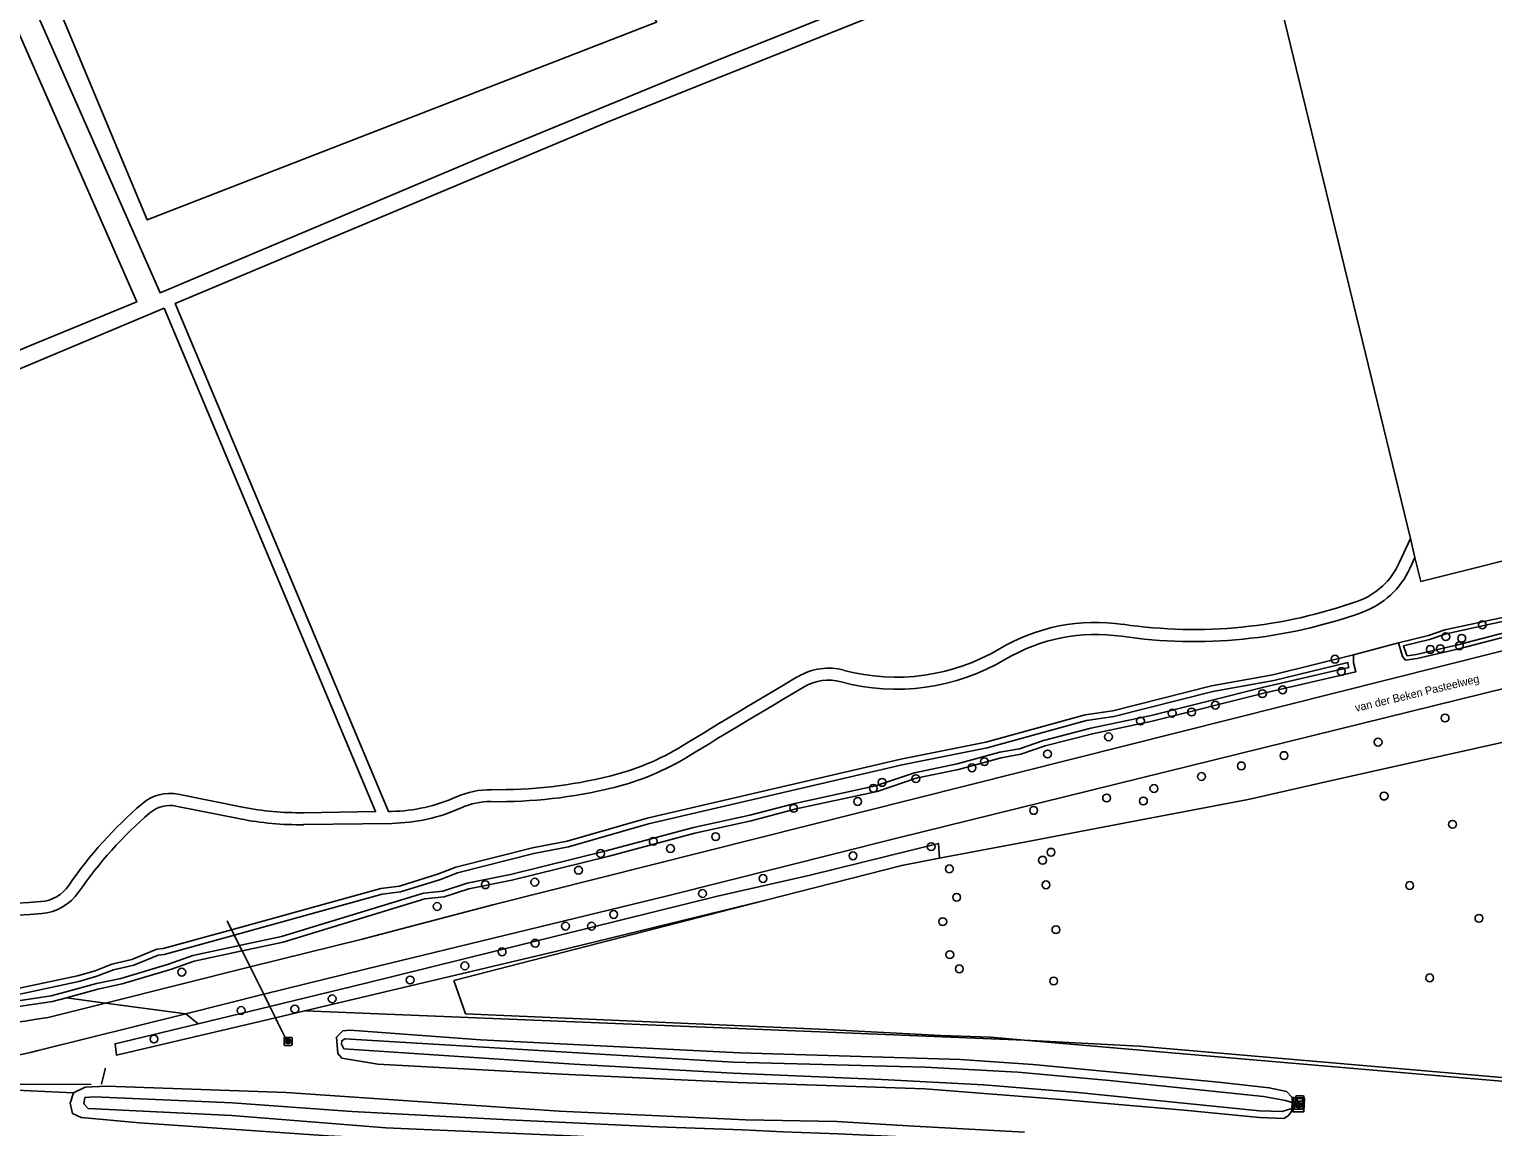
# Model space of a CAD drawing. Extents: x 161486 to 162249, y 379484 to 380829.
# Drawn here: x 161770.8 to 161953.6, y 379616.6 to 379753.8 of the extents above; entities that cross this region are included whole.
import ezdxf

# ---------------------------------------------------------------- set-up
doc = ezdxf.new("R2010")
doc.units = 0
for name, color, linetype in [('IMGEO_Berm_groen', 7, 'Continuous'), ('IMGEO_Boom', 7, 'Continuous'), ('IMGEO_Duiker', 7, 'Continuous'), ('IMGEO_Gemengd_bos', 7, 'Continuous'), ('IMGEO_Grasland_agrarisch', 7, 'Continuous'), ('IMGEO_Grasland_overig', 7, 'Continuous'), ('IMGEO_Groenvoorziening', 7, 'Continuous'), ('IMGEO_Hek', 7, 'Continuous'), ('IMGEO_Muur', 7, 'Continuous'), ('IMGEO_Openbare_ruimte_label', 7, 'Continuous'), ('IMGEO_Rijbaan_lokaal_gesloten', 7, 'Continuous'), ('IMGEO_Rioolput', 7, 'Continuous'), ('IMGEO_Verklikker', 7, 'Continuous'), ('IMGEO_Voetpad_onverhard', 7, 'Continuous'), ('IMGEO_Waterloop', 7, 'Continuous')]:
    doc.layers.add(name, color=color, linetype=linetype)

msp = doc.modelspace()

# ---------------------------------------------------------------- linework, layer by layer
at = {"layer": 'IMGEO_Berm_groen'}
for points in [[(161776.31, 379620.88), (161747.61, 379622.21)], [(161903.07, 379609.91), (161890.48, 379611.42), (161884.77, 379612.02), (161880.37, 379612.14), (161879.91, 379612.17), (161870.14, 379612.44), (161859.41, 379612.86), (161843.4, 379613.94), (161833.41, 379614.24), (161808.13, 379615.48), (161784.56, 379617.12), (161777.24, 379617.78), (161776.19, 379618.3), (161775.89, 379619.59), (161776.31, 379620.88)]]:
    msp.add_lwpolyline(points, dxfattribs=at)
at = {"layer": 'IMGEO_Boom'}
for centre in [(161952.32, 379679.35), (161947.75, 379677.87), (161949.74, 379677.66), (161945.82, 379676.28), (161947.07, 379676.37), (161949.45, 379676.73), (161933.91, 379675.05), (161934.69, 379673.52), (161924.84, 379670.75), (161927.36, 379671.22), (161913.57, 379668.31), (161915.99, 379668.45), (161918.96, 379669.31), (161909.61, 379667.33), (161947.66, 379667.7), (161905.61, 379665.36), (161939.29, 379664.69), (161897.99, 379663.21), (161927.53, 379663.01), (161888.55, 379661.49), (161890.09, 379662.25), (161922.21, 379661.72), (161877.32, 379659.66), (161881.54, 379660.13), (161917.22, 379660.39), (161874.27, 379657.27), (161876.22, 379658.92), (161905.37, 379657.71), (161909.97, 379657.34), (161911.28, 379658.9), (161940.04, 379657.95), (161866.27, 379656.42), (161896.26, 379656.16), (161948.59, 379654.42), (161848.73, 379652.3), (161856.53, 379652.88), (161842.15, 379650.77), (161850.88, 379651.39), (161873.68, 379650.49), (161883.45, 379651.63), (161897.37, 379649.93), (161898.42, 379650.93), (161839.39, 379648.68), (161885.73, 379648.86), (161827.75, 379646.87), (161833.93, 379647.19), (161862.44, 379647.65), (161897.8, 379646.86), (161943.23, 379646.77), (161854.89, 379645.77), (161886.64, 379645.29), (161821.73, 379644.16), (161843.78, 379643.16), (161951.89, 379642.68), (161837.77, 379641.7), (161841.02, 379641.7), (161884.9, 379642.25), (161899.04, 379641.25), (161833.98, 379639.56), (161829.84, 379638.49), (161885.78, 379638.13), (161789.82, 379635.95), (161825.19, 379636.73), (161886.97, 379636.36), (161818.35, 379634.97), (161898.75, 379634.85), (161945.74, 379635.23), (161808.62, 379632.62), (161797.24, 379631.15), (161803.95, 379631.34), (161786.35, 379627.59)]:
    msp.add_circle(centre, 0.489, dxfattribs=at)
at = {"layer": 'IMGEO_Duiker'}
msp.add_lwpolyline([(161803, 379627.29), (161801.8, 379629.69), (161801.52, 379630.26), (161800.82, 379631.67), (161800.07, 379633.18), (161798.36, 379636.6), (161797.37, 379638.6), (161796.05, 379641.24), (161795.5, 379642.36)], dxfattribs=at)
at = {"layer": 'IMGEO_Gemengd_bos'}
for points in [[(161943.9, 379687.78), (161944.62, 379684.78), (162013.75, 379702.1), (161991.56, 379794.76), (161957.01, 379782.13), (161923.86, 379770.32), (161943.32, 379690.14)], [(162103.51, 379717.85), (162082.78, 379712.68), (162051.49, 379704.49), (162044.8, 379703.03), (162038.52, 379701), (162023.08, 379696.83), (162017.46, 379695.48), (162006.48, 379693.16), (162002.89, 379692.16), (162000, 379691.35), (161987.15, 379688.34), (161980.69, 379686.35), (161978.48, 379685.95), (161967.35, 379683.24), (161958.16, 379681.3), (161955.64, 379680.45), (161947.64, 379678.71), (161945.57, 379678.02), (161941.82, 379677.08)], [(161941.82, 379677.08), (161936.2, 379675.58)], [(161936.2, 379675.58), (161926.12, 379673.12), (161918.49, 379671.72), (161906.13, 379668.59), (161902.69, 379668.11), (161890.29, 379664.69), (161879.67, 379662.57), (161847.96, 379655.2), (161837.99, 379652.3), (161833.64, 379651.47), (161824.05, 379649.06), (161821.89, 379648.22), (161817.01, 379646.69), (161814.71, 379646.39), (161796.05, 379641.24), (161787.51, 379638.89), (161786.71, 379638.8), (161783.6, 379637.54), (161781.07, 379636.94), (161778.99, 379636.12), (161776.8, 379635.49), (161768.36, 379633.68)]]:
    msp.add_lwpolyline(points, dxfattribs=at)
at = {"layer": 'IMGEO_Grasland_agrarisch'}
for points in [[(161811.73, 379837.85), (161816.17, 379831.42), (161818.13, 379826.38), (161849.14, 379754.65), (161785.51, 379729.95), (161751.67, 379810.84), (161811.73, 379837.85)], [(162006.1, 379676.56), (162000, 379675.13), (161969.1, 379667.86), (161938.33, 379660.99), (161932.77, 379659.73), (161923.05, 379657.53), (161905.99, 379654.28), (161895.12, 379652.21), (161884.24, 379650.14)], [(161805.2, 379631.13), (161895.06, 379627.46), (161979.42, 379620.21), (162016.57, 379617.14), (162018.11, 379616.78)]]:
    msp.add_lwpolyline(points, dxfattribs=at)
at = {"layer": 'IMGEO_Grasland_overig'}
for points in [[(161895.11, 379615.95), (161880.55, 379616.73), (161871.66, 379617.27), (161860.27, 379617.51), (161836.96, 379618.57), (161802.88, 379620.89), (161780.42, 379621.72), (161777.74, 379621.56), (161776.31, 379620.88)], [(161899.96, 379613.43), (161881.2, 379615.26), (161879.85, 379615.39), (161871.82, 379615.74), (161864.98, 379615.98), (161859.83, 379616.26), (161849.27, 379616.61), (161830.73, 379617.48), (161811.08, 379618.52), (161796.12, 379619.6), (161778.87, 379620.38), (161777.72, 379620.27), (161777.58, 379619.51), (161778.11, 379618.89), (161796.08, 379618.02), (161815.3, 379616.5), (161838.39, 379615.48), (161859.85, 379614.45), (161868.52, 379614.08), (161875.35, 379613.88), (161880.67, 379613.66), (161893.69, 379612.48), (161896.95, 379611.76), (161899.93, 379611.18)]]:
    msp.add_lwpolyline(points, dxfattribs=at)
at = {"layer": 'IMGEO_Groenvoorziening'}
for points in [[(161941.82, 379677.08), (161942.36, 379675.39), (161942.71, 379674.94), (161944.18, 379675.15), (161949.36, 379676.37), (161966.65, 379680.87), (161976.69, 379682.93), (162000, 379688.53), (162003.66, 379689.41), (162005.51, 379689.85), (162013.93, 379691.61), (162022.14, 379693.94), (162040.37, 379698.78), (162051.33, 379701.48), (162056.45, 379702.96), (162079.31, 379708.62), (162080.99, 379708.88), (162100.02, 379713.94), (162104.18, 379714.84)], [(161775.42, 379632.74), (161779.34, 379633.81), (161782.38, 379634.47), (161788.4, 379636.27), (161791.39, 379637.34), (161797.37, 379638.6), (161802.49, 379639.68), (161820.18, 379645.11), (161822.59, 379645.37), (161825.68, 379646.37), (161831.07, 379647.44), (161843.04, 379650.4), (161853.93, 379653.32), (161860.96, 379654.85), (161866.58, 379656.34), (161876.69, 379658.54), (161881.57, 379660.17), (161886.85, 379661.29), (161892.2, 379662.73), (161894.65, 379663.17), (161897.68, 379664.21), (161903.59, 379665.73), (161911.08, 379667.33), (161925.18, 379670.87), (161936.51, 379673.48), (161936.22, 379674.62), (161936.2, 379675.58)], [(161775.42, 379632.74), (161773.67, 379632.26), (161766.6, 379631.24), (161753.61, 379631.05), (161746.01, 379631.6), (161724.64, 379634.37), (161698.92, 379637.34), (161681.11, 379639.62), (161670.75, 379640.73), (161659.13, 379642.24), (161649.61, 379643.11), (161637.41, 379644.57), (161612.43, 379647.27), (161608.11, 379648.09), (161597.22, 379649.61), (161593, 379650.72), (161588.52, 379651.46), (161577.41, 379653.8), (161559.19, 379658.1), (161556.15, 379658.94)], [(161780.29, 379632.09), (161775.42, 379632.74)], [(161791.85, 379629.51), (161790.31, 379630.75)], [(161928.48, 379618.52), (161928.07, 379618.01), (161927.5, 379617.65), (161924.49, 379617.78), (161915.08, 379618.7), (161899.66, 379620.04), (161882.67, 379621.38), (161859.26, 379622.17), (161837.32, 379623.2), (161814.33, 379624.46), (161809.83, 379625.19), (161809.3, 379625.8), (161809.14, 379627.81), (161809.95, 379628.63), (161810.85, 379628.68), (161827.16, 379627.47), (161859.55, 379625.86), (161887.12, 379625.05), (161896.14, 379624.42), (161919.35, 379622.21), (161925.7, 379621.51), (161927.86, 379621.02), (161928.57, 379620.28)], [(161928.77, 379620.27), (161930.09, 379620.21), (161930.02, 379618.51), (161928.68, 379618.51)]]:
    msp.add_lwpolyline(points, dxfattribs=at)
at = {"layer": 'IMGEO_Hek'}
for points in [[(161884.24, 379650.14), (161895.12, 379652.21)], [(161862.64, 379644.89), (161879.78, 379649.29), (161884.24, 379650.14)], [(161823.8, 379634.91), (161862.64, 379644.89)], [(161823.8, 379634.91), (161825.27, 379630.76), (161870.42, 379628.79), (161884.68, 379628.02)], [(161778.49, 379621.89), (161757.2, 379621.98), (161747.3, 379622.52), (161723.65, 379625.11), (161667.75, 379631.4)], [(161895.06, 379627.46), (161909.43, 379626.68), (162017.95, 379617.34)]]:
    msp.add_lwpolyline(points, dxfattribs=at)
at = {"layer": 'IMGEO_Muur'}
for points in [[(161884.68, 379628.02), (161890.86, 379627.82), (161895.06, 379627.46)], [(161780.24, 379623.83), (161779.81, 379621.97)], [(161780.27, 379623.96), (161780.24, 379623.83)], [(161928.5, 379618.92), (161928.54, 379619.66)], [(161928.54, 379619.66), (161928.57, 379620.28)], [(161928.57, 379620.28), (161928.77, 379620.27)], [(161928.77, 379620.27), (161928.68, 379618.51)], [(161928.48, 379618.52), (161928.5, 379618.92)], [(161928.68, 379618.51), (161928.48, 379618.52)]]:
    msp.add_lwpolyline(points, dxfattribs=at)
at = {"layer": 'IMGEO_Rijbaan_lokaal_gesloten'}
for points in [[(161780.29, 379632.09), (161798.36, 379636.6), (161812.36, 379640.09), (161828.7, 379644.34), (162000, 379687.49), (162003.93, 379688.47), (162138.56, 379722.09), (162165.05, 379728.35), (162182.05, 379732.9), (162187.88, 379734.38)], [(162189.91, 379729.16), (162183.27, 379727.53), (162112.09, 379709.59), (162048.1, 379693.81), (162005.31, 379683.53), (162000, 379682.26), (161964.61, 379673.75), (161878.98, 379652.65), (161850.49, 379645.48), (161812.79, 379636.34), (161800.07, 379633.18), (161790.31, 379630.75)], [(161780.29, 379632.09), (161773.12, 379630.3)], [(161790.31, 379630.75), (161780.29, 379632.09)], [(161771.87, 379626.17), (161790.31, 379630.75)]]:
    msp.add_lwpolyline(points, dxfattribs=at)
for centre, radius, start, end in [((161759.05, 379709.89), 80.83, 263.5018, 280.0258), ((161755.94, 379685.62), 61.54, 270.2384, 285.0021)]:
    msp.add_arc(centre, radius, start, end, dxfattribs=at)
at = {"layer": 'IMGEO_Rioolput'}
for p, q in [((161802.6, 379626.88), (161802.6, 379627.73)), ((161802.67, 379627.8), (161803.52, 379627.8)), ((161803.52, 379626.8), (161802.67, 379626.8)), ((161803.08, 379627.58), (161803.11, 379627.58)), ((161803.11, 379627.02), (161803.08, 379627.02)), ((161803.6, 379627.73), (161803.6, 379626.88)), ((161928.86, 379618.88), (161928.86, 379619.73)), ((161928.93, 379619.81), (161929.79, 379619.81)), ((161929.35, 379619.59), (161929.37, 379619.59)), ((161929.86, 379619.73), (161929.86, 379618.88)), ((161929.79, 379618.81), (161928.93, 379618.81)), ((161929.37, 379619.03), (161929.34, 379619.03))]:
    msp.add_line(p, q, dxfattribs=at)
for points in [[(161802.6, 379626.88), (161802.6, 379627.73)], [(161802.67, 379627.8), (161803.52, 379627.8)], [(161803.52, 379626.8), (161802.67, 379626.8)], [(161803.18, 379627.5), (161802.93, 379627.5), (161802.93, 379627.1)], [(161802.93, 379627.1), (161803.06, 379627.1), (161803.06, 379627.26), (161803.07, 379627.26)], [(161803.11, 379627.42), (161803.06, 379627.42), (161803.06, 379627.34)], [(161803.06, 379627.34), (161803.11, 379627.34)], [(161803.11, 379627.23), (161803.19, 379627.1), (161803.32, 379627.1), (161803.26, 379627.23)], [(161803.6, 379627.73), (161803.6, 379626.88)], [(161928.86, 379618.88), (161928.86, 379619.73)], [(161928.93, 379619.81), (161929.79, 379619.81)], [(161929.45, 379619.51), (161929.19, 379619.51), (161929.19, 379619.11)], [(161929.19, 379619.11), (161929.32, 379619.11), (161929.32, 379619.27), (161929.33, 379619.27)], [(161929.37, 379619.43), (161929.32, 379619.43), (161929.32, 379619.35)], [(161929.32, 379619.35), (161929.37, 379619.35)], [(161929.86, 379619.73), (161929.86, 379618.88)], [(161929.79, 379618.81), (161928.93, 379618.81)], [(161929.38, 379619.24), (161929.45, 379619.11), (161929.59, 379619.11), (161929.52, 379619.23)]]:
    msp.add_lwpolyline(points, dxfattribs=at)
for centre, radius, start, end in [((161802.67, 379627.73), 0.0765, 91.552, 178.448), ((161802.67, 379627.73), 0.0765, 91.552, 178.448), ((161802.67, 379626.88), 0.0765, 181.552, 268.448), ((161802.67, 379626.88), 0.0765, 181.552, 268.448), ((161803.07, 379627.21), 0.0533, 26.0293, 88.6989), ((161803.12, 379627.32), 0.0964, 77.0061, 93.1865), ((161803.09, 379627.53), 0.19, 274.7715, 282.9687), ((161803.13, 379627.38), 0.0378, 276.6634, 79.6772), ((161803.18, 379627.39), 0.109, 350.3612, 89.416), ((161803.18, 379627.39), 0.112, 277.5842, 350.9817), ((161803.17, 379627.17), 0.108, 29.5134, 73.7905), ((161803.52, 379627.73), 0.0765, 1.552, 88.448), ((161803.52, 379627.73), 0.0765, 1.552, 88.448), ((161803.52, 379626.88), 0.0765, 271.552, 358.448), ((161803.52, 379626.88), 0.0765, 271.552, 358.448), ((161928.93, 379619.73), 0.0765, 91.552, 178.448), ((161928.93, 379619.73), 0.0765, 91.552, 178.448), ((161929.33, 379619.22), 0.0533, 26.0293, 88.6989), ((161929.38, 379619.33), 0.0964, 77.0061, 93.1865), ((161929.36, 379619.54), 0.19, 274.7715, 282.9687), ((161929.39, 379619.39), 0.0378, 276.6634, 79.6772), ((161929.45, 379619.4), 0.109, 350.3612, 89.416), ((161929.44, 379619.4), 0.112, 277.5842, 350.9817), ((161929.43, 379619.18), 0.108, 29.5134, 73.7905), ((161929.78, 379619.73), 0.0765, 1.552, 88.448), ((161929.78, 379619.73), 0.0765, 1.552, 88.448), ((161928.93, 379618.88), 0.0765, 181.552, 268.448), ((161928.93, 379618.88), 0.0765, 181.552, 268.448), ((161929.78, 379618.88), 0.0765, 271.552, 358.448), ((161929.78, 379618.88), 0.0765, 271.552, 358.448)]:
    msp.add_arc(centre, radius, start, end, dxfattribs=at)
for centre, major_axis, ratio, start_param, end_param in [((161803.08, 379627.3), (-0.387, 0.002), 0.722429, 4.712389, 7.853982), ((161803.11, 379627.3), (-0.39, 0.002), 0.717154, 1.570796, 4.712389), ((161929.35, 379619.31), (-0.387, 0.002), 0.722429, 4.712389, 7.853982), ((161929.37, 379619.31), (-0.39, 0.002), 0.717154, 1.570796, 4.712389)]:
    msp.add_ellipse(centre, major_axis=major_axis, ratio=ratio, start_param=start_param, end_param=end_param, dxfattribs=at)
at = {"layer": 'IMGEO_Verklikker'}
for p, q in [((161929.01, 379619.61), (161929.01, 379620.41)), ((161929.01, 379620.41), (161929.01, 379619.61)), ((161929.11, 379620.51), (161929.9, 379620.51)), ((161929.9, 379620.51), (161929.11, 379620.51)), ((161929.9, 379619.51), (161929.11, 379619.51)), ((161929.11, 379619.51), (161929.9, 379619.51)), ((161930, 379620.41), (161930, 379619.61)), ((161930, 379619.61), (161930, 379620.41))]:
    msp.add_line(p, q, dxfattribs=at)
for points in [[(161929.11, 379620.24), (161929.9, 379620.24), (161929.9, 379619.78), (161929.11, 379619.78), (161929.11, 379620.24)], [(161929.17, 379620.18), (161929.17, 379619.84), (161929.83, 379619.84), (161929.83, 379620.18), (161929.17, 379620.18)]]:
    msp.add_lwpolyline(points, dxfattribs=at)
for centre, start, end in [((161929.11, 379620.41), 90, 180), ((161929.11, 379620.41), 90, 180), ((161929.11, 379619.61), 180, 270), ((161929.11, 379619.61), 180, 270), ((161929.9, 379620.41), 0, 90), ((161929.9, 379620.41), 360, 90), ((161929.9, 379619.61), 270, 0), ((161929.9, 379619.61), 270, 0)]:
    msp.add_arc(centre, 0.1, start, end, dxfattribs=at)
at = {"layer": 'IMGEO_Voetpad_onverhard'}
for points in [[(161724.63, 379863.92), (161744.1, 379818.99), (161749.93, 379805.11), (161787.11, 379720.82), (161827.96, 379738.1), (161856.95, 379750), (161887.59, 379762.26), (161906.05, 379769.39)], [(161816.03, 379656.04), (161815.64, 379656.04), (161788.99, 379719.49), (161843.4, 379742.34), (161885.2, 379759.07), (161901.54, 379765.38), (161916.49, 379771.51), (161986.26, 379800.88), (161991.6, 379802.61), (161991.61, 379803.52), (162063.84, 379834.53), (162092.88, 379846.78), (162125.73, 379861.01), (162124.28, 379863.96)], [(161721.74, 379861.99), (161784.2, 379719.73), (161770.7, 379714.16), (161734.28, 379698.73), (161656.43, 379666.43), (161654.66, 379665.69)], [(161654.35, 379662.95), (161787.61, 379718.91), (161814.03, 379656.01), (161805.03, 379655.87)], [(161943.32, 379690.14), (161941.94, 379687.09)], [(161943.9, 379687.78), (161943.32, 379690.14)], [(161943.3, 379686.47), (161943.9, 379687.78)], [(161797.43, 379656.57), (161789.39, 379658.17)], [(161789.1, 379656.71), (161797.13, 379655.1)], [(161805.05, 379654.38), (161816.05, 379654.54)]]:
    msp.add_lwpolyline(points, dxfattribs=at)
for centre, radius, start, end in [((161933.7, 379690.82), 9.04, 289.6531, 335.6171), ((161933.7, 379690.82), 10.54, 289.6618, 335.6122), ((161916.28, 379739.62), 60.85, 261.6562, 289.6534), ((161904.02, 379656.06), 23.6, 81.661, 120.6636), ((161916.28, 379739.61), 62.35, 261.6535, 289.6543), ((161904.03, 379656.05), 22.1, 81.668, 120.664), ((161879.09, 379698.11), 25.3, 255.0813, 300.6713), ((161879.09, 379698.11), 26.8, 255.0787, 300.6672), ((162446.24, 378690.22), 1140.78, 120.52598, 121.37599), ((161870.64, 379666.4), 7.53, 75.0819, 120.5318), ((161870.64, 379666.4), 6.03, 75.0889, 120.5345), ((162433, 378712.35), 1113.48, 120.51727, 121.38699), ((161835.73, 379691.34), 31.81, 283.7652, 301.3777), ((161835.73, 379691.35), 33.33, 283.7687, 301.3717), ((161829.32, 379717.49), 58.74, 269.1864, 283.769), ((161788.34, 379652.93), 5.35, 78.6939, 130.5962), ((161815.73, 379676.46), 20.42, 270.8523, 294.3071), ((161828.34, 379648.54), 10.21, 89.1508, 114.3028), ((161829.32, 379717.5), 60.25, 269.1834, 283.7643), ((161819.27, 379616.85), 52.87, 130.6022, 145.5048), ((161819.32, 379616.81), 51.43, 130.6108, 145.4973), ((161788.35, 379652.93), 3.85, 78.7359, 130.5589), ((161804.48, 379691.78), 35.91, 258.6758, 270.8756), ((161815.72, 379676.48), 21.94, 270.8732, 294.3044), ((161828.35, 379648.51), 8.75, 89.2095, 114.2631), ((161804.47, 379691.71), 37.34, 258.6703, 270.8965), ((161771.81, 379649.47), 4.73, 274.7901, 325.4619), ((161766.03, 379718.78), 75.77, 256.5143, 274.7679), ((161766.03, 379718.78), 74.28, 256.5143, 274.767), ((161771.8, 379649.48), 6.23, 274.8054, 325.4522)]:
    msp.add_arc(centre, radius, start, end, dxfattribs=at)
at = {"layer": 'IMGEO_Waterloop'}
for points in [[(161966.53, 379681.36), (161949.24, 379676.86), (161947.07, 379676.37), (161944.09, 379675.65), (161942.93, 379675.48), (161942.82, 379675.63), (161942.46, 379676.72), (161945.71, 379677.53), (161947.78, 379678.22), (161955.77, 379679.96)], [(161768.43, 379632.96), (161776.98, 379634.78), (161779.23, 379635.44), (161781.28, 379636.24), (161783.82, 379636.84), (161786.89, 379638.09), (161787.64, 379638.17), (161796.25, 379640.54), (161796.38, 379640.58), (161814.86, 379645.68), (161817.17, 379645.98), (161822.13, 379647.54), (161824.27, 379648.37), (161833.8, 379650.76), (161838.16, 379651.6), (161848.15, 379654.5), (161879.82, 379661.86), (161890.45, 379663.99), (161902.84, 379667.39), (161906.27, 379667.88), (161918.65, 379671.02), (161926.27, 379672.41), (161935.5, 379674.66), (161935.5, 379674.52), (161935.63, 379674.02), (161925.01, 379671.58), (161910.92, 379668.04), (161903.42, 379666.44), (161897.48, 379664.9), (161894.47, 379663.87), (161892.04, 379663.44), (161886.68, 379661.99), (161881.38, 379660.87), (161876.49, 379659.24), (161866.41, 379657.04), (161860.79, 379655.56), (161853.76, 379654.03), (161842.86, 379651.1), (161830.91, 379648.15), (161825.5, 379647.08), (161822.44, 379646.08), (161820.03, 379645.82), (161802.3, 379640.39), (161797.22, 379639.31), (161797.04, 379639.27), (161791.2, 379638.04), (161788.18, 379636.96), (161782.2, 379635.17), (161779.17, 379634.51)], [(161884.24, 379650.14), (161884.49, 379650.2), (161884.35, 379652.03), (161868.34, 379648.07), (161856.75, 379645.45), (161812.82, 379634.56), (161800.82, 379631.67), (161791.85, 379629.51)], [(161884.24, 379650.14), (161879.78, 379649.29), (161862.64, 379644.89), (161836.51, 379638.54), (161805.2, 379631.13)], [(161779.17, 379634.51), (161775.23, 379633.44), (161773.52, 379632.98), (161766.54, 379631.96)], [(161791.85, 379629.51), (161781.49, 379627.01), (161781.65, 379625.59), (161781.83, 379625.6), (161801.52, 379630.26), (161805.2, 379631.13)], [(161928.54, 379619.66), (161927.74, 379619.91), (161924.97, 379620.4), (161905.74, 379622.4), (161894.29, 379623.44), (161882.72, 379624.09), (161858.72, 379624.7), (161810.2, 379627.63), (161809.82, 379627.38), (161809.78, 379626.95), (161810.07, 379626.38), (161838.8, 379624.45), (161858.67, 379623.31), (161877.28, 379622.52), (161890.01, 379621.85), (161901.77, 379620.92), (161924.48, 379618.6), (161927.31, 379618.54), (161928.5, 379618.92)]]:
    msp.add_lwpolyline(points, dxfattribs=at)

# ---------------------------------------------------------------- texts
at = {"layer": 'IMGEO_Openbare_ruimte_label'}
msp.add_text('van der Beken Pasteelweg', height=1, rotation=13.4801, dxfattribs=at).set_placement((161936.54, 379668.47))

doc.saveas('drawing.dxf')
